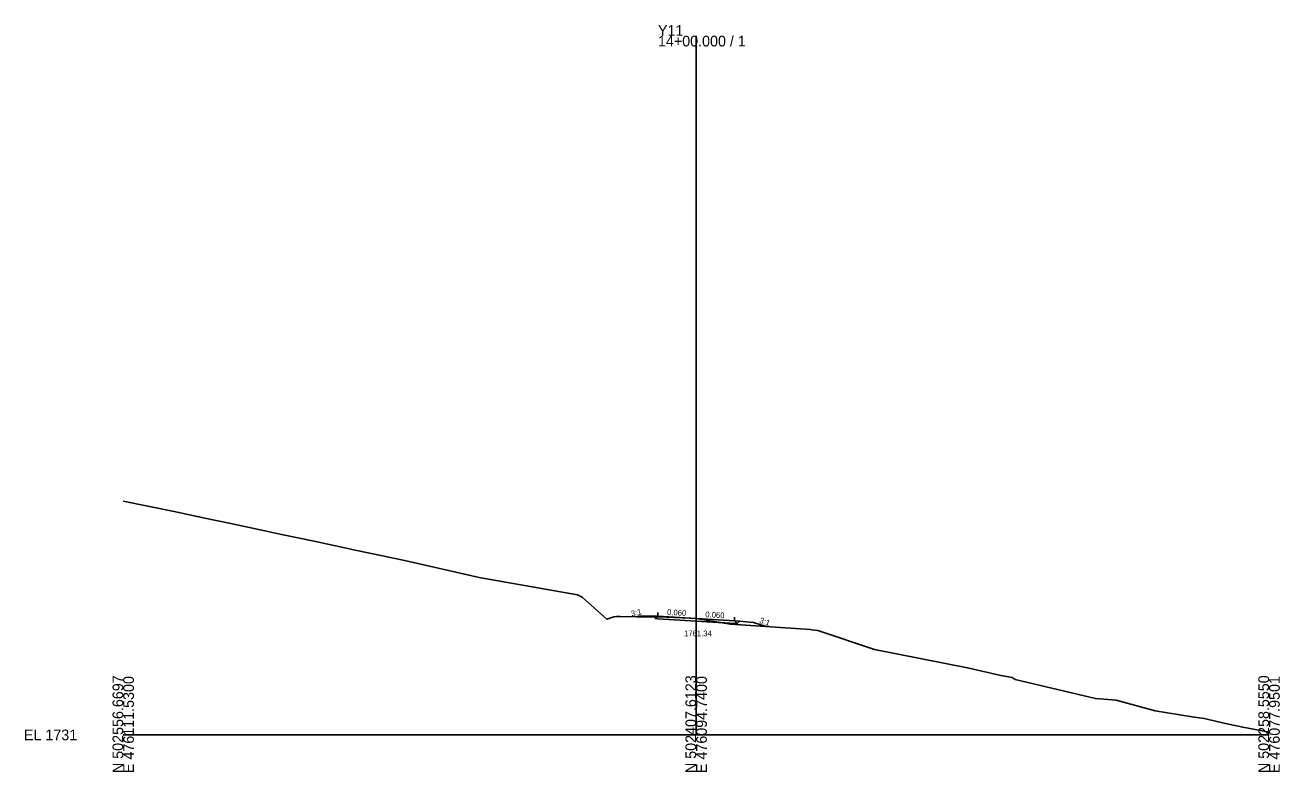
# Model space of a CAD drawing. Extents: x -76 to 353, y -10 to 8186.
# Drawn here: x -25.7 to 302.8, y 7990.3 to 8185.9 of the extents above; entities that cross this region are included whole.
import ezdxf

# ---------------------------------------------------------------- set-up
doc = ezdxf.new("R2010")
doc.units = 0
for name, color, linetype in [('Exist Cross Section Cell', 7, 'Continuous'), ('Exist XS Center Line Elevation Label', 7, 'Continuous'), ('Exist XS Ground Line', 7, 'Continuous'), ('Prop XS Ditch Slope Text', 7, 'Continuous'), ('Prop XS Dump Level', 7, 'Continuous'), ('Prop XS Earthwork Shape', 7, 'Continuous'), ('Prop XS EOT Tick Mark', 7, 'Continuous'), ('Prop XS Finish Grade', 7, 'Continuous'), ('Prop XS Finish Grade Earthwork', 7, 'Continuous'), ('Prop XS Finish Grade Pavement', 7, 'Continuous'), ('Prop XS Pvmt Edge Slope', 7, 'Continuous'), ('Prop XS SE Text', 7, 'Continuous'), ('Prop XS Shoulder Borrow Shape', 7, 'Continuous'), ('Prop XS Side Slope Text', 7, 'Continuous'), ('Prop XS Subgrade Earthwork', 7, 'Continuous')]:
    doc.layers.add(name, color=color, linetype=linetype)

msp = doc.modelspace()

# ---------------------------------------------------------------- linework, layer by layer
at = {"layer": 'Exist Cross Section Cell'}
for p, q in [((150, 8000), (150, 8183.13)), ((0, 8000), (150, 8000)), ((150, 8000), (300, 8000))]:
    msp.add_line(p, q, dxfattribs=at)
at = {"layer": 'Exist XS Ground Line'}
msp.add_lwpolyline([(0, 8061.26), (13.3, 8058.49), (21.34, 8056.79), (27.72, 8055.44), (31.4, 8054.65), (39.06, 8052.99), (41.47, 8052.51), (50.41, 8050.62), (51.53, 8050.39), (60.42, 8048.49), (61.6, 8048.24), (71.19, 8046.22), (74.05, 8045.63), (93.18, 8041.24), (118.96, 8036.67), (120.14, 8036.05), (126.63, 8030.28), (128.46, 8030.95), (129.15, 8030.99), (130.07, 8030.98), (137.94, 8030.92), (140.3, 8030.9), (146.32, 8030.66), (149.99, 8030.51), (158.99, 8028.98), (179.96, 8027.61), (180.27, 8027.56), (181.86, 8027.33), (196.73, 8022.35), (221.08, 8017.59), (229.79, 8015.55), (232.76, 8015.05), (233.57, 8014.47), (254.52, 8009.5), (259.94, 8009.07), (270.18, 8006.32), (279.85, 8004.75), (283.03, 8004.31), (288.61, 8003.02), (293.1, 8002.02), (300, 8000.72)], dxfattribs=at)
at = {"layer": 'Prop XS Dump Level'}
for p, q in [((140, 8031.08), (150, 8030.48)), ((150, 8030.48), (160, 8029.88))]:
    msp.add_line(p, q, dxfattribs=at)
at = {"layer": 'Prop XS Earthwork Shape'}
for points in [[(138.92, 8030.91), (138.74, 8031.08), (135, 8031.08), (134.45, 8030.95), (137.94, 8030.92)], [(146.32, 8030.66), (149.99, 8030.51), (156.28, 8029.44), (150, 8029.82), (140, 8030.42), (139.37, 8030.46), (138.92, 8030.91), (140.3, 8030.9)], [(160.71, 8029.18), (161.31, 8029.78), (165, 8029.48), (168.36, 8028.37), (158.99, 8028.98), (156.28, 8029.44), (160, 8029.22)]]:
    msp.add_lwpolyline(points, close=True, dxfattribs=at)
at = {"layer": 'Prop XS EOT Tick Mark'}
for p, q in [((140, 8031.08), (140, 8032.08)), ((160, 8029.88), (160, 8030.88))]:
    msp.add_line(p, q, dxfattribs=at)
at = {"layer": 'Prop XS Finish Grade'}
for p, q in [((140, 8031.08), (138.74, 8031.08)), ((160, 8029.88), (161.31, 8029.78))]:
    msp.add_line(p, q, dxfattribs=at)
at = {"layer": 'Prop XS Finish Grade Earthwork'}
for p, q in [((135, 8031.08), (134.45, 8030.95)), ((138.74, 8031.08), (135, 8031.08)), ((161.31, 8029.78), (165, 8029.48)), ((165, 8029.48), (168.36, 8028.37))]:
    msp.add_line(p, q, dxfattribs=at)
at = {"layer": 'Prop XS Finish Grade Pavement'}
for p, q in [((140, 8031.08), (150, 8030.48)), ((150, 8030.48), (160, 8029.88))]:
    msp.add_line(p, q, dxfattribs=at)
at = {"layer": 'Prop XS Pvmt Edge Slope'}
for p, q in [((140, 8031.08), (139.37, 8030.46)), ((160, 8029.88), (160.71, 8029.18))]:
    msp.add_line(p, q, dxfattribs=at)
at = {"layer": 'Prop XS Shoulder Borrow Shape'}
for points in [[(139.37, 8030.46), (138.74, 8031.08), (140, 8031.08)], [(139.37, 8030.46), (138.74, 8031.08), (140, 8031.08)], [(139.37, 8030.46), (138.74, 8031.08), (140, 8031.08)], [(139.37, 8030.46), (138.74, 8031.08), (140, 8031.08)], [(160, 8029.88), (160.71, 8029.18), (161.31, 8029.78)], [(160, 8029.88), (160.71, 8029.18), (161.31, 8029.78)]]:
    msp.add_lwpolyline(points, close=True, dxfattribs=at)
at = {"layer": 'Prop XS Subgrade Earthwork'}
for p, q in [((139.37, 8030.46), (138.74, 8031.08)), ((140, 8030.42), (139.37, 8030.46)), ((150, 8029.82), (140, 8030.42)), ((160, 8029.22), (150, 8029.82)), ((160.71, 8029.18), (161.31, 8029.78)), ((160, 8029.22), (160.71, 8029.18))]:
    msp.add_line(p, q, dxfattribs=at)

# ---------------------------------------------------------------- texts
at = {"layer": 'Exist Cross Section Cell'}
for s, p in [('Y11', (140, 8183.13)), ('14+00.000 / 1', (140, 8180.33)), ('EL 1731', (-26, 7998.6))]:
    msp.add_text(s, height=2.8, dxfattribs=at).set_placement(p)
for s, p in [('N 502556.6697', (0, 7990)), ('E 476111.5300', (2.8, 7990)), ('N 502407.6123', (150, 7990)), ('E 476094.7400', (152.8, 7990)), ('N 502258.5550', (300, 7990)), ('E 476077.9501', (302.8, 7990))]:
    msp.add_text(s, height=2.8, rotation=90, dxfattribs=at).set_placement(p)
at = {"layer": 'Exist XS Center Line Elevation Label'}
msp.add_text('1761.34', height=1.5, dxfattribs=at).set_placement((146.85, 8025.84))
at = {"layer": 'Prop XS Ditch Slope Text'}
msp.add_text('3:1', height=1.5, rotation=14.0362, dxfattribs=at).set_placement((133.16, 8030.97))
at = {"layer": 'Prop XS Dump Level'}
for p in [(135, 8031.04), (165, 8029.44)]:
    msp.add_text('Case1', height=0.04, dxfattribs=at).set_placement(p)
at = {"layer": 'Prop XS SE Text'}
for p in [(142.36, 8031.44), (152.36, 8030.84)]:
    msp.add_text('0.060', height=1.5, rotation=356.5664, dxfattribs=at).set_placement(p)
at = {"layer": 'Prop XS Side Slope Text'}
msp.add_text('3:1', height=1.5, rotation=341.5651, dxfattribs=at).set_placement((166.43, 8029.4))

doc.saveas('drawing.dxf')
